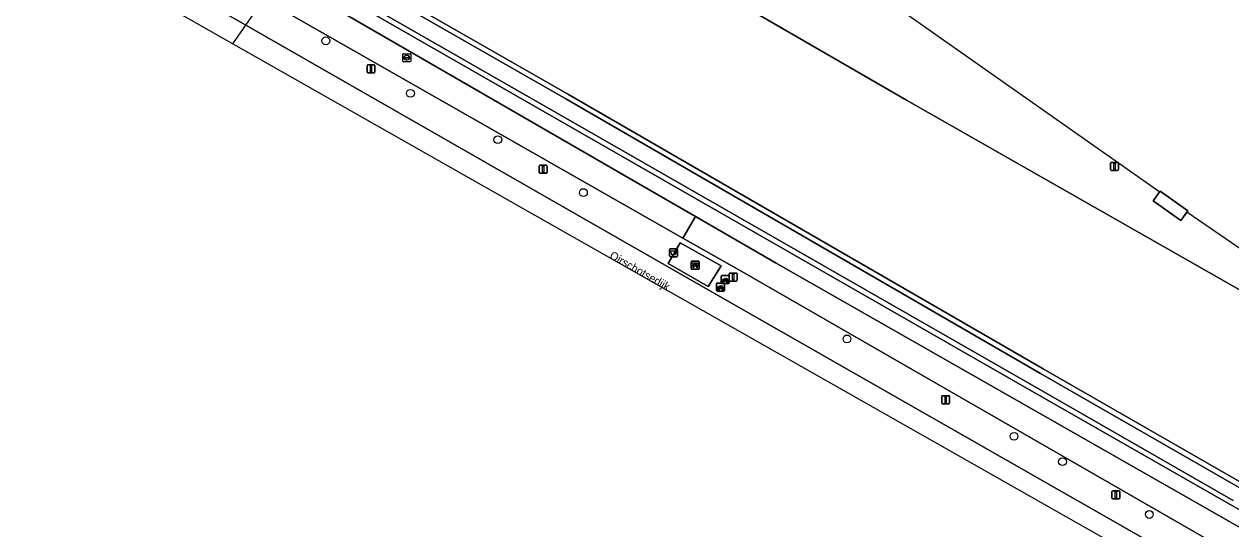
# Model space of a CAD drawing. Extents: x 157132 to 159279, y 384991 to 386650.
# Drawn here: x 158270.6 to 158421.5, y 385376.1 to 385439.2 of the extents above; entities that cross this region are included whole.
import ezdxf

# ---------------------------------------------------------------- set-up
doc = ezdxf.new("R2010")
doc.units = 0
for name, color, linetype in [('IMGEO_Afvalbak', 7, 'Continuous'), ('IMGEO_Bank', 7, 'Continuous'), ('IMGEO_Berm_groen', 7, 'Continuous'), ('IMGEO_Boom', 7, 'Continuous'), ('IMGEO_Brandkraan', 7, 'Continuous'), ('IMGEO_Duiker', 7, 'Continuous'), ('IMGEO_Fietsenrek', 7, 'Continuous'), ('IMGEO_Gemengd_bos', 7, 'Continuous'), ('IMGEO_Groenvoorziening', 7, 'Continuous'), ('IMGEO_Hek', 7, 'Continuous'), ('IMGEO_Lichtmast', 7, 'Continuous'), ('IMGEO_Oever', 7, 'Continuous'), ('IMGEO_Openbare_ruimte_label', 7, 'Continuous'), ('IMGEO_Rijbaan_lokaal_gesloten', 7, 'Continuous'), ('IMGEO_Terreindeel_open', 7, 'Continuous'), ('IMGEO_Voetpad_open', 7, 'Continuous'), ('IMGEO_Waterloop', 7, 'Continuous')]:
    doc.layers.add(name, color=color, linetype=linetype)

msp = doc.modelspace()

# ---------------------------------------------------------------- linework, layer by layer
at = {"layer": 'IMGEO_Afvalbak'}
for p, q in [((158351.33, 385410.26), (158351.33, 385411.06)), ((158351.33, 385411.06), (158351.33, 385410.26)), ((158351.43, 385411.16), (158352.22, 385411.16)), ((158352.22, 385411.16), (158351.43, 385411.16)), ((158352.22, 385410.16), (158351.43, 385410.16)), ((158351.43, 385410.16), (158352.22, 385410.16)), ((158352.32, 385411.06), (158352.32, 385410.26)), ((158352.32, 385410.26), (158352.32, 385411.06))]:
    msp.add_line(p, q, dxfattribs=at)
msp.add_lwpolyline([(158351.47, 385410.88), (158352.18, 385410.88), (158352.03, 385410.4), (158351.62, 385410.4), (158351.47, 385410.88)], dxfattribs=at)
for centre, start, end in [((158351.43, 385411.06), 90, 180), ((158351.43, 385411.06), 90, 180), ((158351.43, 385410.26), 180, 270), ((158351.43, 385410.26), 180, 270), ((158352.22, 385411.06), 0, 90), ((158352.22, 385411.06), 360, 90), ((158352.22, 385410.26), 270, 0), ((158352.22, 385410.26), 270, 0)]:
    msp.add_arc(centre, 0.1, start, end, dxfattribs=at)
at = {"layer": 'IMGEO_Bank'}
for p, q in [((158354.02, 385408.68), (158354.02, 385409.52)), ((158354.02, 385409.52), (158354.02, 385408.68)), ((158354.09, 385409.6), (158354.93, 385409.6)), ((158354.93, 385409.6), (158354.09, 385409.6)), ((158354.94, 385408.6), (158354.1, 385408.6)), ((158354.1, 385408.6), (158354.94, 385408.6)), ((158354.71, 385409), (158354.32, 385409)), ((158354.33, 385409.11), (158354.33, 385409.21)), ((158354.37, 385409.21), (158354.37, 385409.11)), ((158354.66, 385409.22), (158354.38, 385409.22)), ((158354.38, 385409.1), (158354.66, 385409.1)), ((158354.67, 385409.11), (158354.67, 385409.21)), ((158354.71, 385409.21), (158354.71, 385409.11)), ((158355.02, 385409.53), (158355.02, 385408.69)), ((158355.02, 385408.69), (158355.02, 385409.53))]:
    msp.add_line(p, q, dxfattribs=at)
for points in [[(158354.27, 385409), (158354.12, 385409), (158354.23, 385409.1), (158354.32, 385409.1)], [(158354.32, 385409.22), (158354.23, 385409.22), (158354.23, 385409.38), (158354.8, 385409.38), (158354.8, 385409.22), (158354.72, 385409.22)], [(158354.32, 385408.99), (158354.32, 385408.78), (158354.27, 385408.78), (158354.27, 385408.99)], [(158354.72, 385409.1), (158354.8, 385409.1), (158354.91, 385409), (158354.77, 385409)], [(158354.76, 385408.99), (158354.76, 385408.78), (158354.72, 385408.78), (158354.72, 385408.99)]]:
    msp.add_lwpolyline(points, dxfattribs=at)
for centre, radius, start, end in [((158354.1, 385409.52), 0.0779, 92.4484, 184.2845), ((158354.1, 385409.52), 0.0779, 92.4484, 184.2845), ((158354.1, 385408.68), 0.0779, 182.4484, 274.2845), ((158354.1, 385408.68), 0.0779, 182.4484, 274.2845), ((158354.27, 385408.99), 0.00671, 2.8957, 87.1043), ((158354.32, 385409.21), 0.00671, 2.8957, 87.1043), ((158354.32, 385409.11), 0.00671, 272.8957, 357.1043), ((158354.32, 385408.99), 0.00671, 92.8957, 177.1043), ((158354.38, 385409.21), 0.00671, 92.8957, 177.1043), ((158354.38, 385409.11), 0.00671, 182.8957, 267.1043), ((158354.66, 385409.21), 0.00671, 2.8957, 87.1043), ((158354.66, 385409.11), 0.00671, 272.8957, 357.1043), ((158354.72, 385409.21), 0.00671, 92.8957, 177.1043), ((158354.72, 385409.11), 0.00671, 182.8957, 267.1043), ((158354.71, 385408.99), 0.00671, 2.8957, 87.1043), ((158354.77, 385408.99), 0.00671, 92.8957, 177.1043), ((158354.94, 385409.52), 0.0779, 2.4484, 94.2845), ((158354.94, 385409.52), 0.0779, 2.4484, 94.2845), ((158354.94, 385408.68), 0.0779, 272.4484, 4.2845), ((158354.94, 385408.68), 0.0779, 272.4484, 4.2845)]:
    msp.add_arc(centre, radius, start, end, dxfattribs=at)
at = {"layer": 'IMGEO_Berm_groen'}
for points in [[(158285.26, 385451.13), (158176.49, 385513.48), (158101.54, 385556.62), (158075.05, 385571.56), (158073.11, 385568.18), (158356.14, 385406.04), (158513.29, 385316.25)], [(158518.25, 385317.51), (158518.53, 385317.96), (158432.27, 385366.91), (158360.08, 385408.46), (158352.99, 385412.5), (158285.26, 385451.13)]]:
    msp.add_lwpolyline(points, dxfattribs=at)
msp.add_lwpolyline([(158352.64, 385411.89), (158357.76, 385409.01), (158356.15, 385406.45), (158351.16, 385409.31)], close=True, dxfattribs=at)
at = {"layer": 'IMGEO_Boom'}
for centre in [(158308.36, 385437.16), (158318.93, 385430.59), (158329.85, 385424.8), (158340.55, 385418.18), (158373.49, 385399.88), (158394.37, 385387.7), (158400.43, 385384.53), (158411.28, 385377.93)]:
    msp.add_circle(centre, 0.489, dxfattribs=at)
at = {"layer": 'IMGEO_Brandkraan'}
for p, q in [((158317.97, 385434.62), (158317.97, 385435.48)), ((158318.04, 385435.55), (158318.9, 385435.55)), ((158318.9, 385434.55), (158318.04, 385434.55)), ((158318.23, 385435.04), (158318.23, 385435.06)), ((158318.27, 385435.09), (158318.67, 385435.09)), ((158318.67, 385435.01), (158318.27, 385435.01)), ((158318.48, 385434.77), (158318.45, 385434.77)), ((158318.46, 385435.33), (158318.48, 385435.33)), ((158318.71, 385435.06), (158318.71, 385435.04)), ((158318.97, 385435.48), (158318.97, 385434.62))]:
    msp.add_line(p, q, dxfattribs=at)
for points in [[(158317.97, 385434.62), (158317.97, 385435.48)], [(158318.04, 385435.55), (158318.9, 385435.55)], [(158318.9, 385434.55), (158318.04, 385434.55)], [(158318.97, 385435.48), (158318.97, 385434.62)]]:
    msp.add_lwpolyline(points, dxfattribs=at)
for centre, radius, start, end in [((158318.05, 385435.48), 0.0765, 91.552, 178.448), ((158318.05, 385435.48), 0.0765, 91.552, 178.448), ((158318.05, 385434.63), 0.0765, 181.552, 268.448), ((158318.05, 385434.63), 0.0765, 181.552, 268.448), ((158318.27, 385435.05), 0.0403, 85.8775, 175.7526), ((158318.26, 385435.04), 0.0366, 178.938, 274.7102), ((158318.67, 385435.06), 0.0386, 1.7309, 96.639), ((158318.67, 385435.05), 0.043, 264.8664, 352.4533), ((158318.89, 385435.48), 0.0765, 1.552, 88.448), ((158318.89, 385435.48), 0.0765, 1.552, 88.448), ((158318.89, 385434.63), 0.0765, 271.552, 358.448), ((158318.89, 385434.63), 0.0765, 271.552, 358.448)]:
    msp.add_arc(centre, radius, start, end, dxfattribs=at)
for centre, major_axis, ratio, start_param, end_param in [((158318.46, 385435.05), (-0.387, 0.002), 0.722429, 4.712389, 7.853982), ((158318.48, 385435.05), (-0.39, 0.002), 0.717154, 1.570796, 4.712389)]:
    msp.add_ellipse(centre, major_axis=major_axis, ratio=ratio, start_param=start_param, end_param=end_param, dxfattribs=at)
at = {"layer": 'IMGEO_Duiker'}
msp.add_lwpolyline([(158303.54, 385446.74), (158303.12, 385446.13), (158302.29, 385444.92), (158300.57, 385442.42), (158299.34, 385440.63), (158296.71, 385436.8)], dxfattribs=at)
at = {"layer": 'IMGEO_Fietsenrek'}
for p, q in [((158357.78, 385406.87), (158357.78, 385407.71)), ((158357.78, 385407.71), (158357.78, 385406.87)), ((158357.86, 385407.8), (158358.7, 385407.8)), ((158358.7, 385407.8), (158357.86, 385407.8)), ((158357.91, 385406.88), (158357.95, 385407.04)), ((158357.98, 385407.03), (158357.94, 385406.88)), ((158358.02, 385407.05), (158358.02, 385407.06)), ((158358.06, 385406.88), (158358.03, 385407.02)), ((158358.05, 385407.06), (158358.05, 385407.06)), ((158358.06, 385407.03), (158358.09, 385406.88)), ((158358.47, 385407.35), (158358.51, 385407.25)), ((158358.78, 385407.72), (158358.78, 385406.88)), ((158358.78, 385406.88), (158358.78, 385407.72)), ((158357.19, 385405.95), (158357.19, 385406.79)), ((158357.19, 385406.79), (158357.19, 385405.95)), ((158357.26, 385406.87), (158358.1, 385406.87)), ((158358.1, 385406.87), (158357.26, 385406.87)), ((158358.11, 385405.87), (158357.27, 385405.87)), ((158357.27, 385405.87), (158358.11, 385405.87)), ((158357.31, 385405.96), (158357.35, 385406.12)), ((158357.35, 385405.96), (158357.31, 385405.96)), ((158357.38, 385406.1), (158357.35, 385405.96)), ((158357.42, 385406.13), (158357.42, 385406.13)), ((158357.46, 385405.96), (158357.43, 385406.1)), ((158357.45, 385406.14), (158357.46, 385406.13)), ((158357.46, 385406.1), (158357.5, 385405.96)), ((158357.5, 385405.96), (158357.46, 385405.96)), ((158358.71, 385406.8), (158357.87, 385406.8)), ((158357.87, 385406.8), (158358.71, 385406.8)), ((158357.87, 385406.42), (158357.91, 385406.32)), ((158357.94, 385406.88), (158357.91, 385406.88)), ((158358.09, 385406.88), (158358.06, 385406.88)), ((158358.18, 385406.8), (158358.18, 385405.96)), ((158358.18, 385405.96), (158358.18, 385406.8))]:
    msp.add_line(p, q, dxfattribs=at)
for points in [[(158358.12, 385407.27), (158358.06, 385407.18), (158358.02, 385407.15), (158358.03, 385407.2), (158358.08, 385407.3)], [(158358.1, 385407.32), (158358.19, 385407.49), (158358.28, 385407.47), (158358.28, 385407.46), (158358.22, 385407.45), (158358.2, 385407.41), (158358.45, 385407.37)], [(158358.39, 385407.08), (158358.34, 385407.08), (158358.15, 385407.33), (158358.13, 385407.3)], [(158358.44, 385407.34), (158358.18, 385407.38), (158358.16, 385407.35), (158358.33, 385407.13), (158358.44, 385407.34)], [(158358.49, 385407.24), (158358.46, 385407.32), (158358.35, 385407.1), (158358.39, 385407.1)], [(158358.52, 385407.22), (158358.57, 385407.08), (158358.42, 385407.08)], [(158358.42, 385407.1), (158358.54, 385407.1), (158358.5, 385407.21)], [(158358.45, 385407.37), (158358.48, 385407.41), (158358.47, 385407.42), (158358.45, 385407.42), (158358.43, 385407.43), (158358.43, 385407.43), (158358.44, 385407.44), (158358.53, 385407.42), (158358.53, 385407.41), (158358.52, 385407.4), (158358.51, 385407.39), (158358.5, 385407.4), (158358.47, 385407.35)], [(158357.52, 385406.34), (158357.47, 385406.26), (158357.43, 385406.23), (158357.43, 385406.28), (158357.48, 385406.37)], [(158357.5, 385406.4), (158357.59, 385406.56), (158357.68, 385406.55), (158357.68, 385406.54), (158357.62, 385406.53), (158357.6, 385406.48), (158357.85, 385406.44)], [(158357.79, 385406.15), (158357.74, 385406.15), (158357.55, 385406.4), (158357.53, 385406.37)], [(158357.84, 385406.42), (158357.58, 385406.46), (158357.57, 385406.43), (158357.73, 385406.21), (158357.84, 385406.42)], [(158357.89, 385406.32), (158357.86, 385406.39), (158357.75, 385406.18), (158357.79, 385406.18)], [(158357.92, 385406.3), (158357.97, 385406.15), (158357.82, 385406.15)], [(158357.82, 385406.18), (158357.94, 385406.18), (158357.9, 385406.29)], [(158357.85, 385406.44), (158357.88, 385406.49), (158357.87, 385406.49), (158357.85, 385406.5), (158357.84, 385406.51), (158357.84, 385406.51), (158357.84, 385406.51), (158357.93, 385406.5), (158357.94, 385406.49), (158357.93, 385406.48), (158357.91, 385406.47), (158357.9, 385406.47), (158357.87, 385406.42)]]:
    msp.add_lwpolyline(points, dxfattribs=at)
for centre, radius, start, end in [((158357.86, 385407.72), 0.0779, 92.4484, 184.2845), ((158357.86, 385407.72), 0.0779, 92.4484, 184.2845), ((158358.02, 385407.18), 0.159, 62.6766, 242.1369), ((158358.02, 385407.18), 0.129, 63.3192, 238.903), ((158358, 385407.05), 0.0499, 12.8025, 158.6934), ((158358.02, 385407.18), 0.159, 253.9967, 271.7867), ((158358, 385407.05), 0.0174, 12.8025, 163.4502), ((158358.02, 385407.18), 0.129, 253.415, 269.0204), ((158358.02, 385407.18), 0.129, 283.6043, 43.4302), ((158358.02, 385407.18), 0.159, 283.5766, 46.6042), ((158358.55, 385407.1), 0.159, 187.0065, 105.7708), ((158358.55, 385407.1), 0.159, 113.3408, 178.3217), ((158358.55, 385407.1), 0.129, 188.6715, 104.5883), ((158358.55, 385407.1), 0.129, 113.923, 177.9556), ((158358.7, 385407.72), 0.0779, 2.4484, 94.2845), ((158358.7, 385407.72), 0.0779, 2.4484, 94.2845), ((158357.26, 385406.79), 0.0779, 92.4484, 184.2845), ((158357.26, 385406.79), 0.0779, 92.4484, 184.2845), ((158357.26, 385405.95), 0.0779, 182.4484, 274.2845), ((158357.26, 385405.95), 0.0779, 182.4484, 274.2845), ((158357.43, 385406.26), 0.159, 62.6766, 242.1369), ((158357.43, 385406.26), 0.129, 63.3192, 238.903), ((158357.4, 385406.13), 0.0499, 12.8025, 158.6934), ((158357.43, 385406.26), 0.159, 253.9967, 271.7867), ((158357.4, 385406.13), 0.0174, 12.8025, 163.4502), ((158357.43, 385406.26), 0.129, 253.415, 269.0204), ((158357.43, 385406.26), 0.159, 283.5766, 46.6042), ((158357.43, 385406.26), 0.129, 283.6043, 43.4302), ((158357.86, 385406.87), 0.0779, 182.4484, 274.2845), ((158357.86, 385406.87), 0.0779, 182.4484, 274.2845), ((158357.95, 385406.17), 0.159, 187.0065, 105.7708), ((158357.95, 385406.17), 0.159, 113.3408, 178.3217), ((158357.95, 385406.17), 0.129, 188.6715, 104.5883), ((158357.95, 385406.17), 0.129, 113.923, 177.9556), ((158358.11, 385406.79), 0.0779, 2.4484, 94.2845), ((158358.11, 385406.79), 0.0779, 2.4484, 94.2845), ((158358.11, 385405.95), 0.0779, 272.4484, 4.2845), ((158358.11, 385405.95), 0.0779, 272.4484, 4.2845), ((158358.7, 385406.87), 0.0779, 272.4484, 4.2845), ((158358.7, 385406.87), 0.0779, 272.4484, 4.2845)]:
    msp.add_arc(centre, radius, start, end, dxfattribs=at)
at = {"layer": 'IMGEO_Gemengd_bos'}
for points in [[(158380.94, 385429.76), (158361.67, 385440.85), (158340.99, 385452.75), (158257.33, 385500.02), (158193.33, 385537.17), (158082.3, 385600.97), (158084.03, 385605.99), (158080.12, 385603.49), (158080.76, 385603.09), (158081.69, 385602.53), (158080.63, 385600.8), (158079.61, 385601.43), (158079.07, 385601.76), (158077.11, 385600.39)], [(158080, 385578.2), (158127.7, 385551.21), (158180.29, 385521.19), (158197.07, 385511.61), (158217.1, 385500), (158338.67, 385430.45), (158398.01, 385396.13), (158399.37, 385395.35), (158500, 385337.56)], [(158474, 385376.7), (158380.94, 385429.76)]]:
    msp.add_lwpolyline(points, dxfattribs=at)
at = {"layer": 'IMGEO_Groenvoorziening'}
for points in [[(158066.27, 385587.53), (158069.87, 385592.72), (158068.12, 385593.76), (158063.35, 385586.49), (158063.02, 385586.6), (158061.89, 385584.85), (158061.14, 385583.49), (158076.27, 385574.72), (158076.52, 385575.14), (158076.95, 385574.88), (158076.71, 385574.47), (158105.42, 385557.82), (158183.67, 385513.05), (158236.14, 385482.72), (158260.68, 385468.75), (158287.4, 385454.04), (158354.57, 385415.19), (158364.64, 385409.37), (158500.66, 385331.77), (158520.35, 385320.63), (158522.86, 385324.36), (158522.18, 385324.77), (158520.94, 385323.51)], [(158452, 385361.87), (158421.45, 385379.13), (158397.77, 385392.7), (158303.54, 385446.74), (158210.59, 385500), (158178.61, 385518.44), (158148.23, 385535.97), (158078.39, 385575.67)], [(158432.42, 385507.98), (158416.72, 385518.92), (158396.83, 385490.71), (158361.67, 385440.85), (158380.94, 385429.76), (158474, 385376.7)]]:
    msp.add_lwpolyline(points, dxfattribs=at)
msp.add_lwpolyline([(158415.24, 385414.68), (158411.78, 385417.14), (158412.65, 385418.35), (158416.1, 385415.89)], close=True, dxfattribs=at)
at = {"layer": 'IMGEO_Hek'}
for points in [[(158412.45, 385418.32), (158374.11, 385445.34), (158416.02, 385506.85)], [(158361.67, 385440.85), (158380.94, 385429.76), (158474, 385376.7), (158500, 385359.29)], [(158424.36, 385409.98), (158416.09, 385415.67)]]:
    msp.add_lwpolyline(points, dxfattribs=at)
at = {"layer": 'IMGEO_Lichtmast'}
for p, q in [((158313.61, 385434.16), (158314.4, 385434.16)), ((158314.4, 385434.16), (158313.61, 385434.16)), ((158313.51, 385433.26), (158313.51, 385434.06)), ((158313.51, 385434.06), (158313.51, 385433.26)), ((158314.4, 385433.16), (158313.61, 385433.16)), ((158313.61, 385433.16), (158314.4, 385433.16)), ((158314.5, 385434.06), (158314.5, 385433.26)), ((158314.5, 385433.26), (158314.5, 385434.06)), ((158335.02, 385420.7), (158335.02, 385421.5)), ((158335.02, 385421.5), (158335.02, 385420.7)), ((158335.12, 385421.6), (158335.91, 385421.6)), ((158335.91, 385421.6), (158335.12, 385421.6)), ((158335.91, 385420.6), (158335.12, 385420.6)), ((158335.12, 385420.6), (158335.91, 385420.6)), ((158336.01, 385421.5), (158336.01, 385420.7)), ((158336.01, 385420.7), (158336.01, 385421.5)), ((158406.43, 385421.06), (158406.43, 385421.86)), ((158406.43, 385421.86), (158406.43, 385421.06)), ((158406.53, 385421.96), (158407.31, 385421.96)), ((158407.31, 385421.96), (158406.53, 385421.96)), ((158407.31, 385420.96), (158406.53, 385420.96)), ((158406.53, 385420.96), (158407.31, 385420.96)), ((158407.41, 385421.86), (158407.41, 385421.06)), ((158407.41, 385421.06), (158407.41, 385421.86)), ((158358.78, 385407.22), (158358.78, 385408.02)), ((158358.78, 385408.02), (158358.78, 385407.22)), ((158358.88, 385408.12), (158359.67, 385408.12)), ((158359.67, 385408.12), (158358.88, 385408.12)), ((158359.67, 385407.12), (158358.88, 385407.12)), ((158358.88, 385407.12), (158359.67, 385407.12)), ((158359.77, 385408.02), (158359.77, 385407.22)), ((158359.77, 385407.22), (158359.77, 385408.02)), ((158385.33, 385391.88), (158385.33, 385392.68)), ((158385.33, 385392.68), (158385.33, 385391.88)), ((158385.43, 385392.78), (158386.22, 385392.78)), ((158386.22, 385392.78), (158385.43, 385392.78)), ((158386.32, 385392.68), (158386.32, 385391.88)), ((158386.32, 385391.88), (158386.32, 385392.68)), ((158386.22, 385391.78), (158385.43, 385391.78)), ((158385.43, 385391.78), (158386.22, 385391.78)), ((158406.61, 385379.98), (158406.61, 385380.78)), ((158406.61, 385380.78), (158406.61, 385379.98)), ((158406.71, 385380.88), (158407.5, 385380.88)), ((158407.5, 385380.88), (158406.71, 385380.88)), ((158407.5, 385379.88), (158406.71, 385379.88)), ((158406.71, 385379.88), (158407.5, 385379.88)), ((158407.6, 385380.78), (158407.6, 385379.98)), ((158407.6, 385379.98), (158407.6, 385380.78))]:
    msp.add_line(p, q, dxfattribs=at)
for points in [[(158313.93, 385434.04), (158314.08, 385434.04), (158314.08, 385433.29), (158313.93, 385433.29), (158313.93, 385434.04)], [(158335.44, 385421.47), (158335.59, 385421.47), (158335.59, 385420.72), (158335.44, 385420.72), (158335.44, 385421.47)], [(158406.85, 385421.83), (158407, 385421.83), (158407, 385421.08), (158406.85, 385421.08), (158406.85, 385421.83)], [(158359.2, 385408), (158359.35, 385408), (158359.35, 385407.25), (158359.2, 385407.25), (158359.2, 385408)], [(158385.75, 385392.65), (158385.9, 385392.65), (158385.9, 385391.9), (158385.75, 385391.9), (158385.75, 385392.65)], [(158407.03, 385380.75), (158407.18, 385380.75), (158407.18, 385380), (158407.03, 385380), (158407.03, 385380.75)]]:
    msp.add_lwpolyline(points, dxfattribs=at)
for centre, start, end in [((158313.61, 385434.06), 90, 180), ((158313.61, 385434.06), 90, 180), ((158314.4, 385434.06), 0, 90), ((158314.4, 385434.06), 360, 90), ((158313.61, 385433.26), 180, 270), ((158313.61, 385433.26), 180, 270), ((158314.4, 385433.26), 270, 0), ((158314.4, 385433.26), 270, 0), ((158335.12, 385421.5), 90, 180), ((158335.12, 385421.5), 90, 180), ((158335.12, 385420.7), 180, 270), ((158335.12, 385420.7), 180, 270), ((158335.91, 385421.5), 0, 90), ((158335.91, 385421.5), 360, 90), ((158335.91, 385420.7), 270, 0), ((158335.91, 385420.7), 270, 0), ((158406.53, 385421.86), 90, 180), ((158406.53, 385421.86), 90, 180), ((158406.53, 385421.06), 180, 270), ((158406.53, 385421.06), 180, 270), ((158407.31, 385421.86), 0, 90), ((158407.31, 385421.86), 360, 90), ((158407.31, 385421.06), 270, 0), ((158407.31, 385421.06), 270, 0), ((158358.88, 385408.02), 90, 180), ((158358.88, 385408.02), 90, 180), ((158358.88, 385407.22), 180, 270), ((158358.88, 385407.22), 180, 270), ((158359.67, 385408.02), 0, 90), ((158359.67, 385408.02), 360, 90), ((158359.67, 385407.22), 270, 0), ((158359.67, 385407.22), 270, 0), ((158385.43, 385392.68), 90, 180), ((158385.43, 385392.68), 90, 180), ((158386.22, 385392.68), 0, 90), ((158386.22, 385392.68), 360, 90), ((158385.43, 385391.88), 180, 270), ((158385.43, 385391.88), 180, 270), ((158386.22, 385391.88), 270, 0), ((158386.22, 385391.88), 270, 0), ((158406.71, 385380.78), 90, 180), ((158406.71, 385380.78), 90, 180), ((158406.71, 385379.98), 180, 270), ((158406.71, 385379.98), 180, 270), ((158407.5, 385380.78), 0, 90), ((158407.5, 385380.78), 360, 90), ((158407.5, 385379.98), 270, 0), ((158407.5, 385379.98), 270, 0)]:
    msp.add_arc(centre, 0.1, start, end, dxfattribs=at)
at = {"layer": 'IMGEO_Oever'}
for points in [[(158079.72, 385577.61), (158127.38, 385550.64), (158179.96, 385520.62), (158196.74, 385511.05), (158216.77, 385499.43), (158338.34, 385429.89), (158397.69, 385395.57), (158399.05, 385394.78), (158499.67, 385336.99)], [(158520.94, 385323.51), (158522.18, 385324.77), (158500, 385337.56), (158399.37, 385395.35), (158398.01, 385396.13), (158338.67, 385430.45), (158217.1, 385500), (158197.07, 385511.61), (158180.29, 385521.19), (158127.7, 385551.21), (158080, 385578.2)], [(158421.77, 385379.69), (158398.1, 385393.27), (158303.87, 385447.31), (158210.91, 385500.57), (158178.94, 385519.01), (158148.56, 385536.53), (158078.78, 385576.21)], [(158078.39, 385575.67), (158148.23, 385535.97), (158178.61, 385518.44), (158210.59, 385500), (158303.54, 385446.74), (158397.77, 385392.7), (158421.45, 385379.13), (158452, 385361.87), (158500, 385334.39), (158514.58, 385326.04), (158519.78, 385323.32)]]:
    msp.add_lwpolyline(points, dxfattribs=at)
at = {"layer": 'IMGEO_Rijbaan_lokaal_gesloten'}
for points in [[(157962.15, 385631.65), (157960.39, 385628.61), (158092.75, 385552.64), (158517.19, 385311.58), (158723.57, 385194.36), (159060.52, 384999.64)], [(158513.29, 385316.25), (158356.14, 385406.04), (158073.11, 385568.18), (158072.74, 385567.53), (158072.31, 385567.78), (158072.68, 385568.43), (158060.23, 385575.56), (158049.13, 385581.9), (158016.2, 385600.76), (158013.74, 385602.42), (157999.98, 385610.05), (157979.21, 385622.1)]]:
    msp.add_lwpolyline(points, dxfattribs=at)
at = {"layer": 'IMGEO_Terreindeel_open'}
msp.add_lwpolyline([(158357.76, 385409.01), (158352.64, 385411.89), (158351.16, 385409.31), (158356.15, 385406.45)], close=True, dxfattribs=at)
at = {"layer": 'IMGEO_Voetpad_open'}
msp.add_lwpolyline([(158059.85, 385580.13), (158074.61, 385571.81), (158074.69, 385571.95), (158075.12, 385571.7), (158075.05, 385571.56), (158101.54, 385556.62), (158176.49, 385513.48), (158285.26, 385451.13), (158352.99, 385412.5), (158354.57, 385415.19), (158287.4, 385454.04)], dxfattribs=at)
for points in [[(158416.1, 385415.89), (158412.65, 385418.35), (158411.78, 385417.14), (158415.24, 385414.68)], [(158364.64, 385409.37), (158354.57, 385415.19), (158352.99, 385412.5), (158360.08, 385408.46), (158432.27, 385366.91), (158518.53, 385317.96), (158520.35, 385320.63), (158500.66, 385331.77)]]:
    msp.add_lwpolyline(points, close=True, dxfattribs=at)
at = {"layer": 'IMGEO_Waterloop'}
for points in [[(158499.67, 385336.99), (158399.05, 385394.78), (158397.69, 385395.57), (158338.34, 385429.89), (158216.77, 385499.43), (158196.74, 385511.05), (158179.96, 385520.62), (158127.38, 385550.64), (158079.72, 385577.61)], [(158078.78, 385576.21), (158148.56, 385536.53), (158178.94, 385519.01), (158210.91, 385500.57), (158303.87, 385447.31), (158398.1, 385393.27), (158421.77, 385379.69)]]:
    msp.add_lwpolyline(points, dxfattribs=at)

# ---------------------------------------------------------------- texts
at = {"layer": 'IMGEO_Openbare_ruimte_label'}
msp.add_text('Oirschotsedijk', height=1, rotation=330.2054, dxfattribs=at).set_placement((158343.72, 385410.04))

doc.saveas('drawing.dxf')
